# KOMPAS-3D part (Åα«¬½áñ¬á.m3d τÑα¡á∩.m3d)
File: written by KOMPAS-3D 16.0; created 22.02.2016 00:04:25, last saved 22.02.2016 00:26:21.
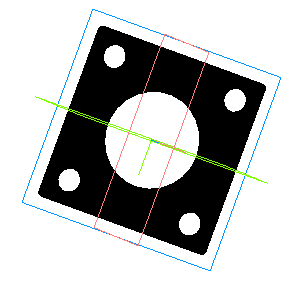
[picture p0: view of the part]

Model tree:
1. Эскиз:1
2. Операция выдавливания:1
     Расстояние 1 = 1.5
3. Скругление:1
     Радиус = 1
4. Скругление:2
     Радиус = 1
5. Скругление:3
     Радиус = 1
6. Скругление:4
     Радиус = 1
